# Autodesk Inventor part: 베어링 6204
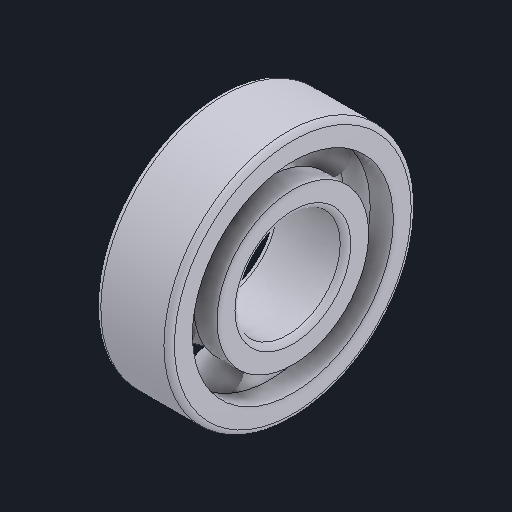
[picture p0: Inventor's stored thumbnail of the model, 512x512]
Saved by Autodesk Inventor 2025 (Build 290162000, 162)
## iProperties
Created: 2025-08
Part Number: 베어링 6204
Material: 강철, 연강
Description: 깊은 그루브 볼 베어링
Document SubType Name: Modeling
Designer: infra005
Density: 7.86 g/cm^3
Appearance: 기본값
Author: jhkim
Sending System: Autodesk Inventor 2026
Preprocessor: ST-DEVELOPER v20.1
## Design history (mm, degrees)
feature "Solid1"
feature "Solid1:1"
feature "Solid1:2"
feature "Solid1:3"
feature "Solid1:4"
feature "Solid1:5"
feature "Solid1:6"
feature "Solid1:7"
feature "Solid1:8"
node "솔리드1"
node "솔리드2"
node "솔리드3"
node "솔리드4"
node "솔리드5"
node "솔리드6"
node "솔리드7"
node "솔리드8"
node "솔리드9"
